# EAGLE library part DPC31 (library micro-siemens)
DPC31 Siemens PROFIBUS-DP Controller mit C31 Core Suurce: dpc31_d.pdf
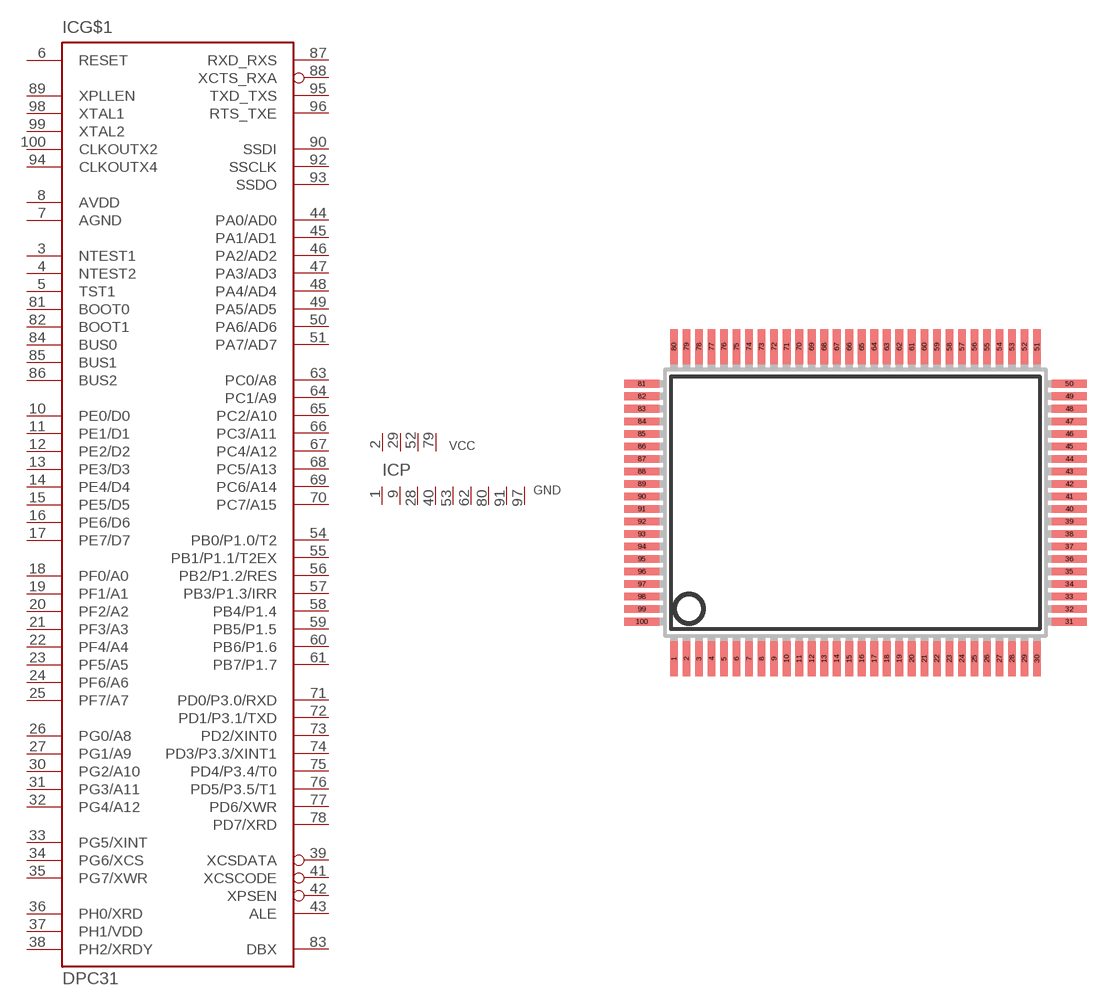
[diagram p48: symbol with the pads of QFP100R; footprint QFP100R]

Designator prefix IC; gates G$1=DPC31 P=DPC31-P

## DPC31 (OC_FARNELL: unknown; OC_NEWARK: unknown)  [QFP100R]
1  P:GND  pwr
2  P:VCC  pwr
3  G$1:NTEST1  in
4  G$1:NTEST2  in
5  G$1:TST1  in
6  G$1:RESET  in
7  G$1:AGND  pwr
8  G$1:AVDD  pwr
9  P:GND  pwr
10  G$1:PE0/D0
11  G$1:PE1/D1
12  G$1:PE2/D2
13  G$1:PE3/D3
14  G$1:PE4/D4
15  G$1:PE5/D5
16  G$1:PE6/D6
17  G$1:PE7/D7
18  G$1:PF0/A0  in
19  G$1:PF1/A1  in
20  G$1:PF2/A2  in
21  G$1:PF3/A3  in
22  G$1:PF4/A4  in
23  G$1:PF5/A5  in
24  G$1:PF6/A6  in
25  G$1:PF7/A7  in
26  G$1:PG0/A8  in
27  G$1:PG1/A9  in
28  P:GND  pwr
29  P:VCC  pwr
30  G$1:PG2/A10  in
31  G$1:PG3/A11  in
32  G$1:PG4/A12  in
33  G$1:PG5/XINT  out
34  G$1:PG6/XCS  in
35  G$1:PG7/XWR  in
36  G$1:PH0/XRD  in
37  G$1:PH1/VDD  in
38  G$1:PH2/XRDY  out
39  G$1:XCSDATA  out
40  P:GND  pwr
41  G$1:XCSCODE  out
42  G$1:XPSEN  out
43  G$1:ALE  out
44  G$1:PA0/AD0
45  G$1:PA1/AD1
46  G$1:PA2/AD2
47  G$1:PA3/AD3
48  G$1:PA4/AD4
49  G$1:PA5/AD5
50  G$1:PA6/AD6
51  G$1:PA7/AD7
52  P:VCC  pwr
53  P:GND  pwr
54  G$1:PB0/P1.0/T2
55  G$1:PB1/P1.1/T2EX
56  G$1:PB2/P1.2/RES
57  G$1:PB3/P1.3/IRR
58  G$1:PB4/P1.4
59  G$1:PB5/P1.5
60  G$1:PB6/P1.6
61  G$1:PB7/P1.7
62  P:GND  pwr
63  G$1:PC0/A8  out
64  G$1:PC1/A9  out
65  G$1:PC2/A10  out
66  G$1:PC3/A11  out
67  G$1:PC4/A12  out
68  G$1:PC5/A13  out
69  G$1:PC6/A14  out
70  G$1:PC7/A15  out
71  G$1:PD0/P3.0/RXD
72  G$1:PD1/P3.1/TXD
73  G$1:PD2/XINT0
74  G$1:PD3/P3.3/XINT1
75  G$1:PD4/P3.4/T0
76  G$1:PD5/P3.5/T1
77  G$1:PD6/XWR
78  G$1:PD7/XRD
79  P:VCC  pwr
80  P:GND  pwr
81  G$1:BOOT0  in
82  G$1:BOOT1  in
83  G$1:DBX  in
84  G$1:BUS0  in
85  G$1:BUS1  in
86  G$1:BUS2  in
87  G$1:RXD_RXS  in
88  G$1:XCTS_RXA  in
89  G$1:XPLLEN  in
90  G$1:SSDI  in
91  P:GND  pwr
92  G$1:SSCLK  out
93  G$1:SSDO  out
94  G$1:CLKOUTX4  out
95  G$1:TXD_TXS  out
96  G$1:RTS_TXE  out
97  P:GND  pwr
98  G$1:XTAL1  in
99  G$1:XTAL2  out
100  G$1:CLKOUTX2  out

## Footprint QFP100R (pad centres in mm)
Quad Flat Pack Package 100 Pin Rectangle Source: Siemens dpc31_d.pdf
smd 0.4 x 1.8: 1 -9.425,-8.1; 2 -8.775,-8.1; 3 -8.125,-8.1; 4 -7.475,-8.1; 5 -6.825,-8.1; 6 -6.175,-8.1; 7 -5.525,-8.1; 8 -4.875,-8.1; 9 -4.225,-8.1; 10 -3.575,-8.1; 11 -2.925,-8.1; 12 -2.275,-8.1; 13 -1.625,-8.1; 14 -0.975,-8.1; 15 -0.325,-8.1; 16 0.325,-8.1; 17 0.975,-8.1; 18 1.625,-8.1; 19 2.275,-8.1; 20 2.925,-8.1; 21 3.575,-8.1; 22 4.225,-8.1; 23 4.875,-8.1; 24 5.525,-8.1; 25 6.175,-8.1; 26 6.825,-8.1; 27 7.475,-8.1; 28 8.125,-8.1; 29 8.775,-8.1; 30 9.425,-8.1; 51 9.425,8.1; 52 8.775,8.1; 53 8.125,8.1; 54 7.475,8.1; 55 6.825,8.1; 56 6.175,8.1; 57 5.525,8.1; 58 4.875,8.1; 59 4.225,8.1; 60 3.575,8.1; 61 2.925,8.1; 62 2.275,8.1; 63 1.625,8.1; 64 0.975,8.1; 65 0.325,8.1; 66 -0.325,8.1; 67 -0.975,8.1; 68 -1.625,8.1; 69 -2.275,8.1; 70 -2.925,8.1; 71 -3.575,8.1; 72 -4.225,8.1; 73 -4.875,8.1; 74 -5.525,8.1; 75 -6.175,8.1; 76 -6.825,8.1; 77 -7.475,8.1; 78 -8.125,8.1; 79 -8.775,8.1; 80 -9.425,8.1
smd 1.8 x 0.4: 31 11.1,-6.175; 32 11.1,-5.525; 33 11.1,-4.875; 34 11.1,-4.225; 35 11.1,-3.575; 36 11.1,-2.925; 37 11.1,-2.275; 38 11.1,-1.625; 39 11.1,-0.975; 40 11.1,-0.325; 41 11.1,0.325; 42 11.1,0.975; 43 11.1,1.625; 44 11.1,2.275; 45 11.1,2.925; 46 11.1,3.575; 47 11.1,4.225; 48 11.1,4.875; 49 11.1,5.525; 50 11.1,6.175; 81 -11.1,6.175; 82 -11.1,5.525; 83 -11.1,4.875; 84 -11.1,4.225; 85 -11.1,3.575; 86 -11.1,2.925; 87 -11.1,2.275; 88 -11.1,1.625; 89 -11.1,0.975; 90 -11.1,0.325; 91 -11.1,-0.325; 92 -11.1,-0.975; 93 -11.1,-1.625; 94 -11.1,-2.275; 95 -11.1,-2.925; 96 -11.1,-3.575; 97 -11.1,-4.225; 98 -11.1,-4.875; 99 -11.1,-5.525; 100 -11.1,-6.175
